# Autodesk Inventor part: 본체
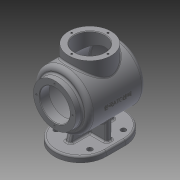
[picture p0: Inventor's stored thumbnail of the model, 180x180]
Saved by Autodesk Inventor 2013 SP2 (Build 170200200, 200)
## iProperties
Created: 2023-01
Part Number: 본체
Material: Generic
Document SubType Name: Modeling
Designer: i
Density: 1 g/cm^3
Author: i
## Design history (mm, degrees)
sketch "스케치1"
  geometry: L1 (-63, 0)-(59, 0); L2 (-63, 0)-(-63, 50); L3 (-63, 50)-(48.087, 50); L4 (-63, 27)-(-46, 27); L5 (-46, 27)-(-46, 45); L6 (-46, 45)-(44.83, 45); A1 r 120 centre (-61, 0) between (59, 0) and (48.087, 50); A2 r 115 centre (-61, 0) between (54, 0) and (44.83, 45); 1 further point
  constraints: 12 end point, 4 point on circle, 3 perpendicular, 3 point on line, 2 centre point, 2 horizontal alignment, 1 coincident, 1 horizontal, 1 parallel
  dimensions: "d0" = 122 distance of L1.start L1.end; "d1" = 59 distance of point (0, 0) L1.end; "d2" = 100 diameter of L3 L1; "d3" = 17 distance of L4.start L4.end; "d4" = 54 diameter of L4 L1; "d5" = 90 diameter of L6 L1; "d6" = 240 diameter of A1; "d7" = 230 diameter of A2
revolve "회전1" sketch "스케치1" stored, may be unused: angle "d8" = 90 deg
sketch "스케치2"
  geometry: C1 r 50 at (0, 0) reference; C2 r 27 at (0, 0) reference; C3 r 38 at (0, 0)
  constraints: 1 centre point, 1 coincident
  dimensions: "d9" = 76 diameter of C3
extrude "돌출1" cut sketch "스케치2" distance "d10" = 12; taper "d11" = 0 deg
sketch "스케치3"
  geometry: C1 r 38 at (0, 0) reference; 1 further point
  constraints: 1 vertical alignment
  dimensions: "d12" = 32.5 distance of C1.centre point (0, 32.5)
hole "구멍1" sketch "스케치3" at (0, 32.5) diameter "d13" = 3.242; stored, may be unused: countersink angle "d17" = 90 deg, drill point angle "d19" = 118 deg; dims "d14" = 8, "d15" = 4, "d16" = 2, "d18" = 10
node "작업 평면1"
sketch "스케치4"
  geometry: C1 r 38 at (0, 0); 1 further point
  constraints: 1 centre point, 1 coincident
  dimensions: "d24" = 76 diameter of C1
extrude "돌출2" join sketch "스케치4" stored distance "d25" = 12; taper "d26" = 0 deg
sketch "스케치5"
  geometry: C1 r 38 at (0, 0) reference; C2 r 27 at (0, 0)
  constraints: 1 centre point, 1 coincident
  dimensions: "d27" = 54 diameter of C2
extrude "돌출3" cut sketch "스케치5" stored distance "d28" = 12; taper "d29" = 0 deg
sketch "스케치6"
  geometry: C1 r 27 at (0, 0) reference; 1 further point
  constraints: 1 vertical alignment
  dimensions: "d30" = 32.5 distance of C1.centre point (0, 32.5)
hole "구멍2" sketch "스케치6" at (0, 32.5) diameter "d31" = 3.242; stored, may be unused: countersink angle "d35" = 90 deg, drill point angle "d37" = 118 deg; dims "d32" = 8, "d33" = 4, "d34" = 2, "d36" = 10
chamfer "모따기1" distance "d41" = 1; stored, may be unused: second distance "d42" = 2, angle "d43" = 45 deg
node "작업 평면2"
sketch "스케치7"
  geometry: L1 (63, -38)-(63, 38) reference; L2 (63, -46)-(-63, -46); L3 (-63, -46)-(-63, 46); L4 (-63, 46)-(63, 46); L5 (63, 46)-(63, -46); 3 further points
  constraints: 8 end point, 2 midpoint, 2 parallel, 1 horizontal, 1 horizontal alignment, 1 perpendicular, 1 vertical alignment
  dimensions: "d45" = 126 distance of L3.end L4.end; "d46" = 92 distance of L2.end L3.end
extrude "돌출4" join sketch "스케치7" distance "d47" = 10; taper "d48" = 0 deg
fillet "모깎기1" dims "d49" = 46
sketch "스케치8"
  geometry: L1 (-5, 35)-(5, 35); L2 (5, 35)-(5, -35); L3 (5, -35)-(-5, -35); L4 (-5, -35)-(-5, 35); 3 further points
  constraints: 8 end point, 2 midpoint, 2 parallel, 1 horizontal, 1 horizontal alignment, 1 perpendicular, 1 vertical alignment
  dimensions: "d50" = 10 distance of L2.end L3.end; "d51" = 70 distance of L1.end L2.end
extrude "돌출5" join sketch "스케치8" stored distance "d52" = 10; taper "d53" = 0 deg
sketch "스케치9"
  geometry: L1 (-53, -34.121)-(-52.026, -32.5) reference; L2 (-52.026, -32.5)-(-53, -30.879) reference; L3 (-53, -30.879)-(-63, -30.879) reference; L4 (-63, -30.879)-(-63, -28) reference; L5 (-63, -28)-(-62, -27) reference; L6 (-62, -27)-(-46, -27) reference; L7 (-46, -27)-(-46, -45) reference; L8 (-46, -45)-(44.83, -45) reference; L9 (44.83, 45)-(27, 45) reference; L10 (27, 45)-(27, 63) reference; L11 (27, 63)-(28, 64) reference; L12 (28, 64)-(30.879, 64) reference; L13 (30.879, 64)-(30.879, 54) reference; L14 (30.879, 54)-(32.5, 53.026) reference; L15 (32.5, 53.026)-(34.121, 54) reference; L16 (34.121, 54)-(34.121, 64) reference; L17 (34.121, 64)-(38, 64) reference; L18 (38, 64)-(38, 50) reference; L19 (38, 50)-(48.087, 50) reference; L20 (48.087, -50)-(5, -50) reference; L21 (5, -50)-(5, -70) reference; L22 (5, -70)-(63, -70) reference; L23 (63, -70)-(63, -80) reference; L24 (63, -80)-(-63, -80) reference; L25 (-63, -80)-(-63, -70) reference; L26 (-63, -70)-(-5, -70) reference; L27 (-5, -70)-(-5, -50) reference; L28 (-5, -50)-(-51, -50) reference; L29 (-51, -50)-(-51, -38) reference; L30 (-51, -38)-(-63, -38) reference; L31 (-63, -38)-(-63, -34.121) reference; L32 (-63, -34.121)-(-53, -34.121) reference; L33 (-52.026, 32.5)-(-53, 34.121) reference; L34 (-53, 34.121)-(-63, 34.121) reference; L35 (-63, 34.121)-(-63, 38) reference; L36 (-63, 38)-(-51, 38) reference; L37 (-51, 38)-(-51, 50) reference; L38 (-51, 50)-(-38, 50) reference; L39 (-38, 50)-(-38, 64) reference; L40 (-38, 64)-(-34.121, 64) reference; L41 (-34.121, 64)-(-34.121, 54) reference; L42 (-34.121, 54)-(-32.5, 53.026) reference; L43 (-32.5, 53.026)-(-30.879, 54) reference; L44 (-30.879, 54)-(-30.879, 64) reference; L45 (-30.879, 64)-(-28, 64) reference; L46 (-28, 64)-(-27, 63) reference; L47 (-27, 63)-(-27, 45) reference; L48 (-27, 45)-(-46, 45) reference; L49 (-46, 45)-(-46, 27) reference; L50 (-46, 27)-(-62, 27) reference; L51 (-62, 27)-(-63, 28) reference; L52 (-63, 28)-(-63, 30.879) reference; L53 (-63, 30.879)-(-53, 30.879) reference; L54 (-53, 30.879)-(-52.026, 32.5) reference; L55 (-34.641, -50)-(-40, -70); A1 r 115 centre (-61, 0) between (44.83, -45) and (44.83, 45) reference; A2 r 120 centre (-61, 0) between (48.087, -50) and (48.087, 50) reference; 1 further point
  constraints: 2 end point, 2 point on line
  dimensions: "d55" = 23 distance of L25.end L55.end; "d56" = 105 deg angle of L26 L55
feature "리브1" sketch "스케치9" dims "d57" = 1, "d58" = 10, "d59" = 0, "d60" = 0, "d61" = 1, "d62" = 1
fillet "모깎기2" dims "d63" = 3
sketch "스케치10"
  geometry: 5 further points
  constraints: 2 horizontal alignment, 2 vertical alignment
  dimensions: "d64" = 60 distance of point (30, 30) point (-30, 30); "d66" = 60 distance of point (-30, -30) point (-30, 30); "d67" = 30 horizontal distance of point (0, 0) point (-30, 30); "d68" = 30 horizontal distance of point (0, 0) point (-30, 30)
hole "구멍3" sketch "스케치10" at (-30, 30), (30, 30), (-30, -30), (30, -30) diameter "d69" = 9; stored, may be unused: countersink angle "d73" = 90 deg, drill point angle "d75" = 118 deg; dims "d70" = 8, "d71" = 4, "d72" = 2, "d74" = 10
fillet "모깎기3" dims "d76" = 8
fillet "모깎기4" dims "d77" = 3
fillet "모깎기5" dims "d78" = 3
fillet "모깎기6" dims "d79" = 3
node "작업 평면3"
sketch "스케치11"
  geometry: L1 (63, -80)-(17, -80) reference; L2 (-63, 38)-(-63, -38) reference; 2 further points
  constraints: 1 other
  dimensions: "d81" = 80 distance from line of L1 point (0, 0); "d82" = 63 distance from line of L2 point (0, 0)
feature "엠보싱1" sketch "스케치11" dims "d0" = 122, "d1" = 59, "d2" = 100, "d3" = 17, "d4" = 54, "d5" = 90, "d6" = 240, "d7" = 230, "d83" = 0.5, "d84" = 0
node "솔리드1"
pattern_circular "원형 패턴1" dims angle "d21" = 360 deg
pattern_circular "원형 패턴2" dims angle "d39" = 360 deg
mirror "대칭1"
node "절단 모서리 투영1"
other parameters: "d23" = 64
